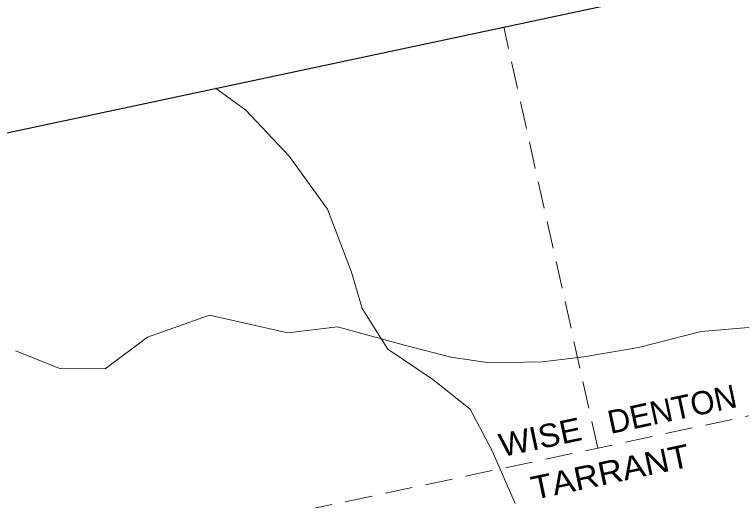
# Model space of a CAD drawing. Extents: x 2357218 to 2371708, y 6973728 to 6980157.
# Drawn here: x 2371225.3 to 2371385.2, y 6977747.8 to 6977854.6 of the extents above; entities that cross this region are included whole.
import ezdxf

# ---------------------------------------------------------------- set-up
doc = ezdxf.new("R2010")
doc.units = 0
doc.header["$LTSCALE"] = 2
doc.linetypes.add('MEDIUM_DASHED', pattern=[4.5, 3, -1.5])
doc.layers.add('62', color=7, linetype='Continuous', lineweight=13)
doc.layers.add('63', color=7, linetype='Continuous', lineweight=13)

msp = doc.modelspace()

# ---------------------------------------------------------------- linework, layer by layer
at = {"layer": '62', "lineweight": 25}
msp.add_line((2371171.482, 6977817.538), (2371611.249, 6977911.015), dxfattribs=at)
at = {"layer": '62', "linetype": 'MEDIUM_DASHED'}
for p, q in [((2371353.615, 6977759.286), (2371332.929, 6977851.854)), ((2371629.67, 6977817.964), (2371191.201, 6977724.765))]:
    msp.add_line(p, q, dxfattribs=at)
at = {"layer": '62'}
for p, q in [((2371235.244, 6977776.777), (2371225.54, 6977780.651)), ((2371245.287, 6977776.819), (2371235.244, 6977776.777))]:
    msp.add_line(p, q, dxfattribs=at)
for points in [[(2371269.515, 6977838.377), (2371276.217, 6977833.59), (2371285.694, 6977823.433), (2371294.166, 6977811.801), (2371299.414, 6977797.942), (2371301.802, 6977789.958), (2371307.451, 6977781.015), (2371317.323, 6977774.395), (2371325.524, 6977767.855), (2371330.346, 6977758.69), (2371335.413, 6977747.091)], [(2371245.249, 6977776.671), (2371254.592, 6977783.698), (2371268.184, 6977788.472), (2371285.457, 6977784.597), (2371296.351, 6977785.947), (2371311.122, 6977781.931), (2371321.277, 6977779.282), (2371329.809, 6977778.014), (2371341.37, 6977778.263), (2371350.577, 6977779.324), (2371362.557, 6977781.411), (2371376.353, 6977784.896), (2371394.551, 6977786.416), (2371406.252, 6977788.075), (2371419.724, 6977789.306), (2371435.597, 6977785.958), (2371450.742, 6977782.44), (2371464.719, 6977778.602), (2371481.364, 6977770.639), (2371492.467, 6977765.704), (2371505.806, 6977760.856), (2371513.967, 6977755.573)]]:
    msp.add_lwpolyline(points, dxfattribs=at)
at = {"layer": '63', "lineweight": 25}
msp.add_line((2371171.482, 6977817.538), (2371611.249, 6977911.015), dxfattribs=at)
at = {"layer": '63', "linetype": 'MEDIUM_DASHED'}
for p, q in [((2371353.615, 6977759.286), (2371332.929, 6977851.854)), ((2371629.67, 6977817.964), (2371191.201, 6977724.765))]:
    msp.add_line(p, q, dxfattribs=at)
at = {"layer": '63'}
for p, q in [((2371235.244, 6977776.777), (2371225.54, 6977780.651)), ((2371245.287, 6977776.819), (2371235.244, 6977776.777))]:
    msp.add_line(p, q, dxfattribs=at)
for points in [[(2371269.515, 6977838.377), (2371276.217, 6977833.59), (2371285.694, 6977823.433), (2371294.166, 6977811.801), (2371299.414, 6977797.942), (2371301.802, 6977789.958), (2371307.451, 6977781.015), (2371317.323, 6977774.395), (2371325.524, 6977767.855), (2371330.346, 6977758.69), (2371335.413, 6977747.091)], [(2371245.249, 6977776.671), (2371254.592, 6977783.698), (2371268.184, 6977788.472), (2371285.457, 6977784.597), (2371296.351, 6977785.947), (2371311.122, 6977781.931), (2371321.277, 6977779.282), (2371329.809, 6977778.014), (2371341.37, 6977778.263), (2371350.577, 6977779.324), (2371362.557, 6977781.411), (2371376.353, 6977784.896), (2371394.551, 6977786.416), (2371406.252, 6977788.075), (2371419.724, 6977789.306), (2371435.597, 6977785.958), (2371450.742, 6977782.44), (2371464.719, 6977778.602), (2371481.364, 6977770.639), (2371492.467, 6977765.704), (2371505.806, 6977760.856), (2371513.967, 6977755.573)]]:
    msp.add_lwpolyline(points, dxfattribs=at)

# ---------------------------------------------------------------- texts
at = {"layer": '62'}
msp.add_text('DENTON', height=5.099, rotation=12, dxfattribs=at).set_placement((2371356.414, 6977762.367))
for s, width, p in [('WISE', 1.05, (2371332.533, 6977757.292)), ('TARRANT', 1.1, (2371339.569, 6977747.882))]:
    msp.add_text(s, height=5.099, rotation=12, dxfattribs=dict(at, width=width)).set_placement(p)
at = {"layer": '63'}
msp.add_text('DENTON', height=5.099, rotation=12, dxfattribs=at).set_placement((2371356.414, 6977762.367))
for s, width, p in [('WISE', 1.05, (2371332.533, 6977757.292)), ('TARRANT', 1.1, (2371339.569, 6977747.882))]:
    msp.add_text(s, height=5.099, rotation=12, dxfattribs=dict(at, width=width)).set_placement(p)

doc.saveas('drawing.dxf')
